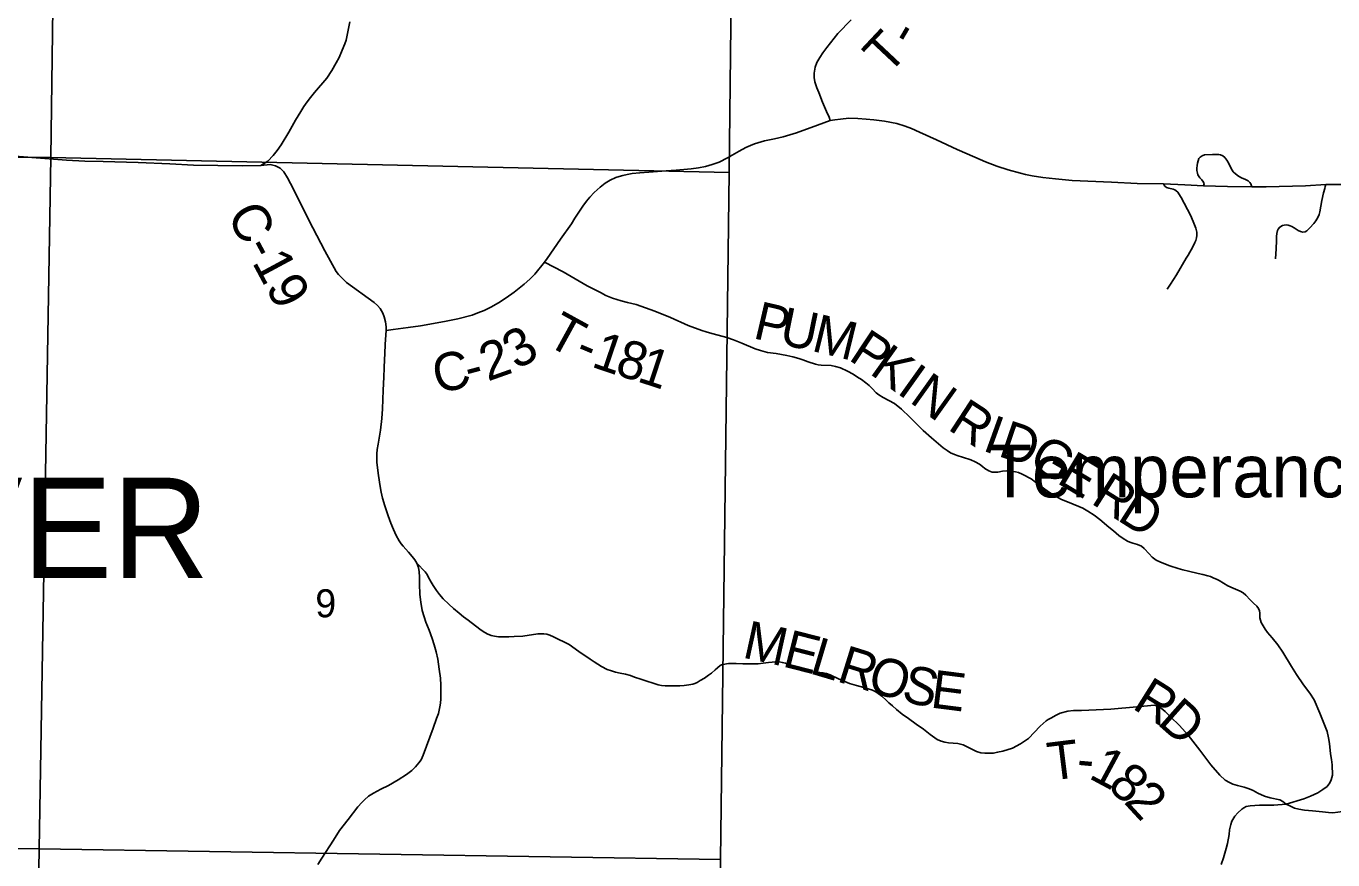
# Model space of a CAD drawing. Extents: x 0 to 34, y 0 to 22.
# Drawn here: x 5.085 to 7.038, y 15.399 to 16.646 of the extents above; entities that cross this region are included whole.
import ezdxf

# ---------------------------------------------------------------- set-up
doc = ezdxf.new("R2010")
doc.units = 0
for name, color, linetype in [('GM_X_Corporation', 7, 'Continuous'), ('GM_X_County_Road', 7, 'Continuous'), ('GM_X_County_Road_Text', 7, 'Continuous'), ('GM_X_Section_Text', 7, 'Continuous'), ('GM_X_State_Route', 7, 'Continuous'), ('GM_X_Township_Road', 7, 'Continuous'), ('GM_X_Township_Road_Text', 7, 'Continuous'), ('GM_X_Township_Text', 7, 'Continuous'), ('GM_X_Unincorporated_Text', 7, 'Continuous')]:
    doc.layers.add(name, color=color, linetype=linetype)

msp = doc.modelspace()

# ---------------------------------------------------------------- linework, layer by layer
at = {"layer": 'GM_X_Corporation'}
for points in [[(4.1176, 17.4733), (5.1353, 17.4571), (5.122, 16.4496), (4.1025, 16.4586)], [(5.1353, 17.4571), (6.147, 17.4393), (6.1357, 16.427), (5.122, 16.4496)], [(5.122, 16.4496), (5.1041, 15.416), (4.0887, 15.4288), (4.1025, 16.4586)], [(6.1357, 16.427), (6.1226, 15.3998), (5.1041, 15.416), (5.122, 16.4496)], [(4.0887, 15.4288), (5.1041, 15.416), (5.088, 14.3982), (4.0718, 14.4088)], [(5.1041, 15.416), (6.1226, 15.3998), (6.117, 14.3875), (5.088, 14.3982)]]:
    msp.add_lwpolyline(points, close=True, dxfattribs=at)
at = {"layer": 'GM_X_County_Road'}
for points in [[(5.623, 16.191), (5.6336, 16.1923), (5.6557, 16.1951), (5.6745, 16.198), (5.7102, 16.2044), (5.7299, 16.2082), (5.7515, 16.2136), (5.7602, 16.217), (5.7695, 16.2208), (5.7794, 16.2259), (5.7909, 16.2324), (5.8025, 16.2397), (5.8141, 16.2481), (5.8293, 16.2603), (5.8375, 16.2673), (5.8454, 16.275), (5.8598, 16.2928), (5.8636, 16.2982), (5.8838, 16.3271), (5.8998, 16.3504), (5.9052, 16.3587), (5.9122, 16.369), (5.9171, 16.3766), (5.9226, 16.3842), (5.9274, 16.3901), (5.9341, 16.3972), (5.943, 16.4049), (5.9504, 16.4109), (5.9578, 16.4155), (5.9664, 16.4194), (5.9712, 16.421), (5.9768, 16.4226), (5.9834, 16.4241), (5.9905, 16.4254), (6.0021, 16.4267), (6.0157, 16.4276), (6.0414, 16.4294), (6.0564, 16.4306), (6.0791, 16.4325), (6.0898, 16.434), (6.1004, 16.4362), (6.1103, 16.439), (6.1205, 16.4426), (6.1333, 16.4487), (6.1508, 16.4588), (6.1604, 16.4643), (6.1673, 16.4673), (6.1736, 16.47), (6.1886, 16.4744), (6.2036, 16.4775), (6.2163, 16.4805), (6.2261, 16.4833), (6.2361, 16.4864), (6.2679, 16.4976), (6.2868, 16.5047), (6.2936, 16.5058), (6.3019, 16.507), (6.3144, 16.5081), (6.3282, 16.5076), (6.3402, 16.507), (6.3519, 16.506), (6.3678, 16.5039), (6.3863, 16.5004), (6.3986, 16.4965), (6.4082, 16.4926), (6.4201, 16.4874), (6.4458, 16.4758), (6.4766, 16.4615), (6.503, 16.4499), (6.5189, 16.4429), (6.5359, 16.4365), (6.5528, 16.4311), (6.5713, 16.426), (6.5787, 16.4242), (6.5888, 16.422), (6.6047, 16.4194), (6.6232, 16.4174), (6.6483, 16.4153), (6.707, 16.4125), (6.7456, 16.4105), (6.7847, 16.4103), (6.8166, 16.4087), (6.8446, 16.407), (6.8807, 16.406), (6.9169, 16.4054), (6.9381, 16.4057), (6.9971, 16.4073), (7.0275, 16.409), (7.0571, 16.4092)], [(5.4354, 16.4375), (5.4494, 16.4388), (5.4578, 16.4371), (5.4645, 16.4337), (5.47, 16.4281), (5.4753, 16.419), (5.4801, 16.4107), (5.5132, 16.3444), (5.5312, 16.3097), (5.5484, 16.2791), (5.5518, 16.2746), (5.5556, 16.2704), (5.5639, 16.2628), (5.605, 16.2327), (5.61, 16.2281), (5.6142, 16.2236), (5.6182, 16.2169), (5.6202, 16.2111), (5.6221, 16.2035), (5.6229, 16.1961), (5.623, 16.191), (5.6217, 16.1706), (5.6208, 16.156), (5.6206, 16.1472), (5.62, 16.1351), (5.6194, 16.1212), (5.6184, 16.1016), (5.6176, 16.0736), (5.6164, 16.0591), (5.6143, 16.0417), (5.6109, 16.0207), (5.6096, 16.0128), (5.6091, 16.0064), (5.6088, 15.999), (5.6089, 15.9933), (5.6113, 15.974), (5.6141, 15.9574), (5.6156, 15.949), (5.6175, 15.9403), (5.621, 15.9285), (5.6258, 15.9137), (5.6299, 15.9029), (5.6339, 15.8931), (5.6379, 15.8844), (5.6424, 15.8762), (5.6455, 15.872), (5.6484, 15.8684), (5.6565, 15.8595), (5.6619, 15.853), (5.6659, 15.8479), (5.669, 15.843), (5.6712, 15.8364), (5.6722, 15.8302), (5.6727, 15.8227), (5.673, 15.8119), (5.6735, 15.7963), (5.6749, 15.7845), (5.677, 15.7721), (5.6798, 15.7625), (5.6824, 15.7545), (5.6847, 15.7485), (5.6872, 15.7429), (5.6918, 15.7302), (5.6949, 15.7207), (5.6977, 15.7103), (5.7, 15.6992), (5.7021, 15.6846), (5.7041, 15.6711), (5.7046, 15.6607), (5.7047, 15.6401), (5.7042, 15.6335), (5.7033, 15.6281), (5.701, 15.6183), (5.6984, 15.6105), (5.6931, 15.5964), (5.6782, 15.5557), (5.6751, 15.549), (5.672, 15.5442), (5.6668, 15.5383), (5.6611, 15.5331), (5.6532, 15.5269), (5.6407, 15.5188), (5.6264, 15.5106), (5.6149, 15.5048), (5.6042, 15.4991), (5.5967, 15.4947), (5.5905, 15.4892), (5.5864, 15.485), (5.5807, 15.4784), (5.5661, 15.4598), (5.5534, 15.443), (5.5444, 15.429), (5.5268, 15.402), (5.5206, 15.3924)]]:
    msp.add_lwpolyline(points, dxfattribs=at)
at = {"layer": 'GM_X_State_Route'}
msp.add_lwpolyline([(5.0621, 16.452), (5.0996, 16.4488), (5.1452, 16.4457), (5.1725, 16.4442), (5.1998, 16.4437), (5.2523, 16.4422), (5.2995, 16.4398), (5.335, 16.4382), (5.3715, 16.4377), (5.4086, 16.4369), (5.4354, 16.4375), (5.4461, 16.4439), (5.4543, 16.4523), (5.4603, 16.4601), (5.4659, 16.4686), (5.4775, 16.4875), (5.4876, 16.5051), (5.4953, 16.518), (5.4999, 16.5255), (5.505, 16.5327), (5.5098, 16.5391), (5.5159, 16.5467), (5.5343, 16.5683), (5.542, 16.5796), (5.5484, 16.591), (5.5527, 16.5991), (5.5573, 16.6098), (5.5613, 16.6193), (5.5631, 16.625), (5.5646, 16.6321), (5.5685, 16.6522)], dxfattribs=at)
at = {"layer": 'GM_X_Township_Road'}
for points in [[(6.2868, 16.5047), (6.2849, 16.5098), (6.281, 16.5181), (6.2754, 16.532), (6.2695, 16.5464), (6.2666, 16.5536), (6.2638, 16.5624), (6.2628, 16.5691), (6.2626, 16.5756), (6.2642, 16.5846), (6.2669, 16.5915), (6.2711, 16.5988), (6.2755, 16.6058), (6.2816, 16.614), (6.2983, 16.6347), (6.3179, 16.6553)], [(6.8446, 16.407), (6.8454, 16.41), (6.8447, 16.4125), (6.8422, 16.416), (6.8392, 16.419), (6.8364, 16.4234), (6.8356, 16.4261), (6.8349, 16.4299), (6.8348, 16.4333), (6.8351, 16.4373), (6.8356, 16.4409), (6.8365, 16.4443), (6.8379, 16.4478), (6.8399, 16.4499), (6.8426, 16.4519), (6.8461, 16.4533), (6.8582, 16.4539), (6.8673, 16.4541), (6.8703, 16.4534), (6.8734, 16.4519), (6.8764, 16.4493), (6.8794, 16.4455), (6.8819, 16.4413), (6.886, 16.4331), (6.8888, 16.4282), (6.8923, 16.4249), (6.8968, 16.4215), (6.9014, 16.419), (6.9075, 16.4164), (6.9114, 16.4145), (6.914, 16.4123), (6.9154, 16.4102), (6.9169, 16.4054)], [(6.7901, 16.2525), (6.7954, 16.26), (6.8045, 16.2742), (6.8188, 16.299), (6.8215, 16.3036), (6.8285, 16.3159), (6.8315, 16.3224), (6.833, 16.3254), (6.8344, 16.3292), (6.8349, 16.333), (6.8346, 16.3378), (6.8332, 16.3438), (6.8292, 16.3538), (6.825, 16.3634), (6.8113, 16.3896), (6.808, 16.3951), (6.8061, 16.3977), (6.804, 16.3996), (6.8018, 16.4011), (6.7993, 16.402), (6.7928, 16.4034), (6.7892, 16.4044), (6.7867, 16.4066), (6.7847, 16.4103)], [(6.9524, 16.298), (6.9534, 16.313), (6.9537, 16.3253), (6.9538, 16.3312), (6.9543, 16.3357), (6.9554, 16.3402), (6.9564, 16.3424), (6.958, 16.3449), (6.9601, 16.3463), (6.9629, 16.3478), (6.9654, 16.3485), (6.9685, 16.3486), (6.9711, 16.3483), (6.9743, 16.3474), (6.9768, 16.3461), (6.9801, 16.3442), (6.9861, 16.3403), (6.9897, 16.3386), (6.9933, 16.3379), (6.9964, 16.3385), (6.999, 16.3397), (7.0036, 16.3443), (7.0096, 16.3508), (7.0128, 16.355), (7.0157, 16.3596), (7.0175, 16.3642), (7.0186, 16.3684), (7.0217, 16.3854), (7.0242, 16.3968), (7.0259, 16.4029), (7.0267, 16.4059), (7.0275, 16.409)], [(5.8598, 16.2928), (5.8874, 16.2786), (5.9235, 16.2577), (5.9431, 16.2475), (5.9513, 16.2432), (5.9562, 16.2411), (5.9615, 16.239), (5.974, 16.2353), (5.9838, 16.2329), (5.9966, 16.2296), (6.0244, 16.2198), (6.0479, 16.2103), (6.0746, 16.1983), (6.0948, 16.1908), (6.1011, 16.1887), (6.1098, 16.1862), (6.119, 16.184), (6.1322, 16.1803), (6.142, 16.1769), (6.1548, 16.1718), (6.1745, 16.1636), (6.1824, 16.1608), (6.1928, 16.1581), (6.2057, 16.1562), (6.2218, 16.1534), (6.2306, 16.1513), (6.2396, 16.1489), (6.2457, 16.1467), (6.2538, 16.1437), (6.2647, 16.1406), (6.2687, 16.1395), (6.2734, 16.139), (6.2881, 16.1387), (6.2945, 16.1371), (6.302, 16.1348), (6.3127, 16.1299), (6.3209, 16.1253), (6.3275, 16.1211), (6.3333, 16.1173), (6.3397, 16.1127), (6.3451, 16.1085), (6.3495, 16.1039), (6.3554, 16.0978), (6.3595, 16.0946), (6.3659, 16.0906), (6.3828, 16.0815), (6.3932, 16.073), (6.4057, 16.0611), (6.4255, 16.0414), (6.4383, 16.0304), (6.4556, 16.0152), (6.4613, 16.0112), (6.4667, 16.0081), (6.4723, 16.0055), (6.4779, 16.0036), (6.4846, 16.0016), (6.4967, 15.9974), (6.5036, 15.9945), (6.5099, 15.991), (6.5141, 15.9875), (6.518, 15.9843), (6.5236, 15.9811), (6.5289, 15.9792), (6.5324, 15.9789), (6.5372, 15.9792), (6.5441, 15.9803), (6.5506, 15.9809), (6.557, 15.9807), (6.5636, 15.9796), (6.5683, 15.9783), (6.5734, 15.9762), (6.5784, 15.9737), (6.583, 15.9712), (6.5869, 15.9689), (6.5936, 15.964), (6.6077, 15.9538), (6.6147, 15.9485), (6.6233, 15.943), (6.6325, 15.9383), (6.644, 15.9338), (6.6644, 15.9254), (6.6719, 15.9209), (6.681, 15.9148), (6.6897, 15.9084), (6.7032, 15.897), (6.7099, 15.8914), (6.7183, 15.8845), (6.7246, 15.8796), (6.731, 15.8758), (6.7347, 15.8743), (6.7388, 15.8729), (6.7462, 15.8707), (6.7518, 15.8681), (6.7559, 15.8649), (6.7635, 15.8569), (6.768, 15.8519), (6.774, 15.8474), (6.7792, 15.8449), (6.7853, 15.8425), (6.7942, 15.8391), (6.8068, 15.835), (6.8138, 15.8331), (6.8223, 15.8308), (6.8369, 15.8275), (6.8438, 15.8262), (6.8512, 15.8242), (6.855, 15.823), (6.8602, 15.8207), (6.8639, 15.8191), (6.8681, 15.8169), (6.8812, 15.8091), (6.8889, 15.8055), (6.8993, 15.801), (6.9037, 15.7984), (6.9078, 15.7949), (6.9144, 15.7881), (6.9194, 15.7833), (6.9243, 15.7784), (6.9267, 15.7751), (6.9282, 15.7717), (6.929, 15.7683), (6.9288, 15.7653), (6.9289, 15.7612), (6.9298, 15.7576), (6.9306, 15.7543), (6.9336, 15.7491), (6.9369, 15.7445), (6.9405, 15.7394), (6.9472, 15.7312), (6.956, 15.7206), (6.9634, 15.7099), (6.9763, 15.6886), (6.9837, 15.6765), (6.9942, 15.6611), (7.0038, 15.6486), (7.0103, 15.6384), (7.0187, 15.6185), (7.0295, 15.5912), (7.0315, 15.5816), (7.033, 15.5732), (7.0345, 15.558), (7.0358, 15.5494), (7.0371, 15.5413), (7.0377, 15.5259), (7.0356, 15.5192), (7.0336, 15.5144), (7.0293, 15.509), (7.0229, 15.5043), (7.0154, 15.4997), (7.0047, 15.4945), (6.9945, 15.4906), (6.9683, 15.4824), (6.9497, 15.481), (6.9282, 15.481), (6.9142, 15.48), (6.9086, 15.4789), (6.9048, 15.4773), (6.9017, 15.4753), (6.8961, 15.4696), (6.8913, 15.4646), (6.8872, 15.4571), (6.8855, 15.4523), (6.8837, 15.444), (6.883, 15.4371), (6.8804, 15.4238), (6.8785, 15.4161), (6.8744, 15.4024), (6.8712, 15.3925)], [(6.124, 15.6907), (6.1224, 15.6901), (6.1181, 15.6866), (6.1148, 15.6833), (6.1094, 15.6786), (6.105, 15.6756), (6.0989, 15.6711), (6.0925, 15.6673), (6.0879, 15.6647), (6.0843, 15.6631), (6.0812, 15.6621), (6.0753, 15.6608), (6.0685, 15.6602), (6.0617, 15.6596), (6.0499, 15.6594), (6.0402, 15.6596), (6.0347, 15.66), (6.0296, 15.6608), (6.0249, 15.6624), (6.0098, 15.6676), (6.002, 15.67), (5.9959, 15.672), (5.9915, 15.6736), (5.988, 15.6748), (5.9806, 15.677), (5.9727, 15.6785), (5.9658, 15.6801), (5.9596, 15.6818), (5.9533, 15.6842), (5.9448, 15.6886), (5.9392, 15.6921), (5.9338, 15.6954), (5.9277, 15.6996), (5.9112, 15.7108), (5.8967, 15.7214), (5.8732, 15.7327), (5.8674, 15.7352), (5.863, 15.7367), (5.8588, 15.7374), (5.855, 15.7375), (5.8496, 15.7371), (5.8272, 15.7339), (5.8145, 15.7331), (5.8061, 15.7328), (5.7974, 15.7326), (5.7908, 15.7329), (5.7851, 15.7336), (5.7801, 15.7348), (5.7741, 15.7373), (5.7682, 15.7409), (5.7631, 15.7441), (5.7455, 15.7577), (5.7387, 15.7629), (5.732, 15.7681), (5.7238, 15.7753), (5.7167, 15.7818), (5.7084, 15.7898), (5.7027, 15.7959), (5.6981, 15.8019), (5.6931, 15.8097), (5.6903, 15.8147), (5.686, 15.8227), (5.6842, 15.8261), (5.6811, 15.8298), (5.669, 15.843)], [(6.9683, 15.4824), (6.9631, 15.4867), (6.9586, 15.4891), (6.9445, 15.4922), (6.9357, 15.4945), (6.9259, 15.4993), (6.9189, 15.503), (6.9128, 15.5056), (6.9055, 15.5081), (6.8957, 15.5107), (6.8887, 15.5127), (6.8837, 15.5148), (6.877, 15.5184), (6.8691, 15.5259), (6.8555, 15.5412), (6.8394, 15.5633), (6.8217, 15.5857), (6.8089, 15.6002), (6.7955, 15.6133), (6.7874, 15.6213), (6.7814, 15.6263), (6.7767, 15.6288), (6.7713, 15.6307), (6.7452, 15.6281), (6.7059, 15.6245), (6.6624, 15.6228), (6.6504, 15.6226), (6.642, 15.6218), (6.6305, 15.6188), (6.6232, 15.6152), (6.6173, 15.6118), (6.6125, 15.6093), (6.6094, 15.6071), (6.6005, 15.599), (6.5833, 15.581), (6.571, 15.5726), (6.5593, 15.5665), (6.5448, 15.5621), (6.5369, 15.5602), (6.5309, 15.559), (6.5255, 15.5589), (6.5179, 15.5589), (6.5119, 15.5595), (6.5052, 15.5615), (6.4964, 15.5657), (6.4856, 15.5711), (6.4774, 15.5731), (6.4706, 15.5737), (6.4633, 15.5745), (6.4582, 15.5754), (6.4524, 15.5768), (6.4468, 15.5795), (6.4363, 15.5866), (6.4262, 15.5947), (6.4153, 15.6022), (6.4035, 15.6108), (6.3944, 15.617), (6.386, 15.6239), (6.3799, 15.6294), (6.3741, 15.6343), (6.3703, 15.638), (6.3639, 15.6441), (6.3564, 15.6494), (6.353, 15.6515), (6.3497, 15.6529), (6.3368, 15.6568), (6.326, 15.6598), (6.3156, 15.6632), (6.2993, 15.67), (6.2868, 15.6762), (6.281, 15.6781), (6.2759, 15.6792), (6.2671, 15.6802), (6.2577, 15.6804), (6.2536, 15.6806), (6.2494, 15.6812), (6.2457, 15.6824), (6.2405, 15.6843), (6.2269, 15.6905), (6.2199, 15.6933), (6.215, 15.6946), (6.2106, 15.6953), (6.2047, 15.6954), (6.1998, 15.6951), (6.1947, 15.6946), (6.1863, 15.6935), (6.1792, 15.6926), (6.1708, 15.6922), (6.1625, 15.6922), (6.1559, 15.6923), (6.1461, 15.6929), (6.1348, 15.6929), (6.1264, 15.6916), (6.124, 15.6907)], [(7.132, 15.4932), (7.1171, 15.485), (7.1113, 15.4834), (7.0946, 15.4798), (7.0842, 15.4777), (7.0636, 15.4731), (7.0456, 15.4705), (7.0382, 15.4698), (7.0317, 15.47), (7.0227, 15.4712), (7.0075, 15.4727), (6.9954, 15.4736), (6.9872, 15.4749), (6.9806, 15.4764), (6.9745, 15.4797), (6.9683, 15.4824)]]:
    msp.add_lwpolyline(points, dxfattribs=at)

# ---------------------------------------------------------------- texts
at = {"layer": 'GM_X_County_Road_Text'}
for s, height, rotation, p in [('C-19', 0.05682, 298.2545, (5.3839, 16.3636)), ('3', 0.0568, 30.5897, (5.8185, 16.1311)), ('2', 0.0568, 19.5484, (5.7747, 16.1143)), ('C', 0.0568, 12.4183, (5.6992, 16.0962)), ('-', 0.0568, 14.9304, (5.7474, 16.1068))]:
    msp.add_text(s, height=height, rotation=rotation, dxfattribs=at).set_placement(p)
at = {"layer": 'GM_X_Section_Text'}
msp.add_text('9', height=0.0419, rotation=0, dxfattribs=at).set_placement((5.5171, 15.762))
at = {"layer": 'GM_X_Township_Road_Text'}
for s, rotation, p in [('T', 46.8124, (6.3729, 16.5713)), ('-', 59.6296, (6.4102, 16.6133)), ('P', 346.8903, (6.1697, 16.1796)), ('T', 331.2438, (5.8593, 16.1711)), ('U', 348.4336, (6.2087, 16.1706)), ('M', 346.2188, (6.2571, 16.1607)), ('P', 326.4694, (6.3123, 16.148)), ('1', 341.1997, (5.9279, 16.1372)), ('8', 343.199, (5.9631, 16.1253)), ('-', 337.1172, (5.9023, 16.1479)), ('1', 341.7329, (5.9962, 16.1153)), ('K', 324.5284, (6.3438, 16.1271)), ('I', 324.4714, (6.3845, 16.0981)), ('N', 324.4739, (6.4035, 16.0846)), ('R', 326.8846, (6.4606, 16.0439)), ('I', 340.1701, (6.5125, 16.012)), ('D', 341.4655, (6.5358, 16.0036)), ('G', 329.6872, (6.5804, 15.989)), ('E', 329.2222, (6.6235, 15.9638)), ('R', 327.6479, (6.6746, 15.9333)), ('D', 327.5204, (6.714, 15.9083)), ('M', 347.6016, (6.1538, 15.7022)), ('E', 345.7361, (6.2136, 15.689)), ('L', 343.4695, (6.2542, 15.6787)), ('R', 342.6944, (6.2948, 15.6667)), ('O', 343.2581, (6.3399, 15.6526)), ('S', 346.7114, (6.3914, 15.6373)), ('E', 352.8017, (6.4352, 15.6273)), ('R', 327.8722, (6.7364, 15.6267)), ('D', 318.4022, (6.7739, 15.6034)), ('T', 7.0681, (6.6149, 15.5176)), ('-', 354.9434, (6.6539, 15.5228)), ('1', 331.7451, (6.6713, 15.5224)), ('8', 318.0043, (6.6992, 15.5079)), ('2', 312.7253, (6.7243, 15.4855))]:
    msp.add_text(s, height=0.0568, rotation=rotation, dxfattribs=at).set_placement(p)
at = {"layer": 'GM_X_Township_Text'}
msp.add_text('BEAVER', height=0.15, rotation=0, dxfattribs=at).set_placement((4.5445, 15.8207))
at = {"layer": 'GM_X_Unincorporated_Text'}
msp.add_text('Temperanceville', height=0.078977, rotation=0, dxfattribs=at).set_placement((6.5238, 15.9413))

doc.saveas('drawing.dxf')
